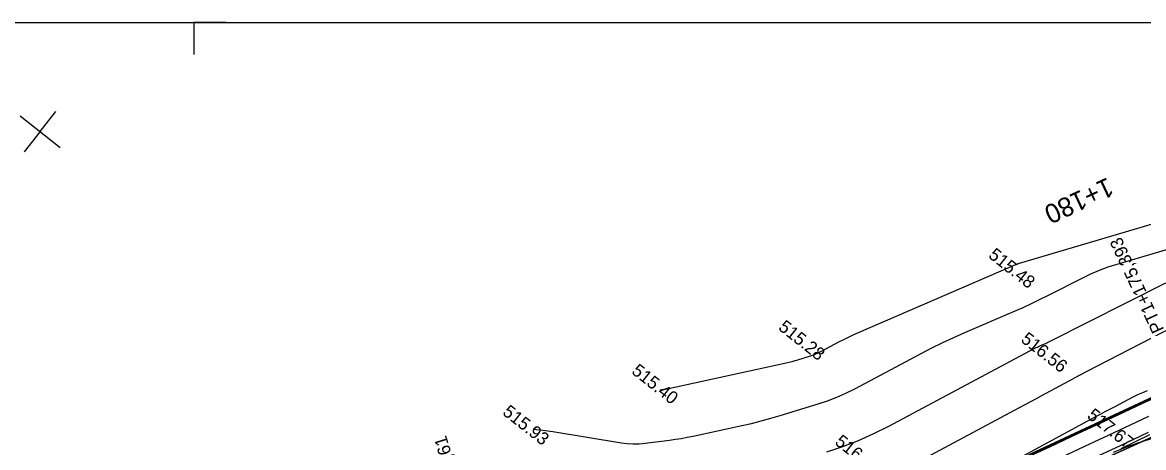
# Model space of a CAD drawing. Extents: x -636600 to -628587, y -1090963 to -1085869.
# Drawn here: x -629664.1 to -629488.6, y -1089625.5 to -1089558.9 of the extents above; entities that cross this region are included whole.
import ezdxf

# ---------------------------------------------------------------- set-up
doc = ezdxf.new("R2010")
doc.units = 0
for name, color, linetype in [('01_PARCELY_NÁVRH_PC', 7, 'Continuous'), ('08_LEGENDA_HV', 7, 'Continuous'), ('42', 7, 'Continuous'), ('Ex_Major Contours', 7, 'Continuous'), ('Ex_Minor Contours', 7, 'Continuous'), ('HEKTOMETRY20', 7, 'Continuous'), ('HL_BODY', 7, 'Continuous'), ('koty_vše', 7, 'Continuous'), ('situace_osa', 7, 'Continuous'), ('situace_těleso', 7, 'Continuous'), ('situace_vozovka', 7, 'Continuous'), ('síť křížků', 7, 'Continuous'), ('VRCHOLY', 7, 'Continuous')]:
    doc.layers.add(name, color=color, linetype=linetype)

msp = doc.modelspace()

# ---------------------------------------------------------------- linework, layer by layer
at = {"layer": '01_PARCELY_NÁVRH_PC'}
for points in [[(-629254.65, -1089739.87), (-629360.83, -1089658.33), (-629368.29, -1089654.33), (-629380.48, -1089650.34), (-629407.53, -1089646.03), (-629420.13, -1089642.95), (-629431.22, -1089638.63), (-629441.36, -1089632.25), (-629463, -1089614.17), (-629469.39, -1089611.97), (-629476.14, -1089612.42), (-629540.5, -1089642.41), (-629554.39, -1089646.51), (-629581.68, -1089651.28), (-629593.36, -1089654.47), (-629629.45, -1089670.47), (-629647.36, -1089680.42), (-629666.29, -1089692.67)], [(-629669.23, -1089703.19), (-629636.5, -1089682.37), (-629594.83, -1089663.56), (-629566.21, -1089655.26), (-629543.03, -1089650.82), (-629502.78, -1089630.85), (-629477.84, -1089619.53), (-629472.37, -1089618.39), (-629466.83, -1089619.34), (-629458.17, -1089625.36), (-629433.24, -1089646.24), (-629378.59, -1089656.96), (-629364.86, -1089662.95), (-629248.8, -1089751.04)]]:
    msp.add_lwpolyline(points, dxfattribs=at)
at = {"layer": '08_LEGENDA_HV'}
msp.add_line((-629847.27, -1089558.93), (-629007.27, -1089558.93), dxfattribs=at)
msp.add_lwpolyline([(-629632.27, -1089558.93), (-629637.27, -1089558.93), (-629637.27, -1089563.93)], dxfattribs=at)
at = {"layer": '42'}
msp.add_line((-629502.78, -1089630.85), (-629476.43, -1089618.89), dxfattribs=at)
at = {"layer": 'Ex_Major Contours'}
msp.add_lwpolyline([(-629488.02, -1089616.61), (-629488.78, -1089616.91), (-629489.54, -1089617.25), (-629490.28, -1089617.61), (-629493.22, -1089619.13), (-629493.96, -1089619.51), (-629494.69, -1089619.89), (-629495.42, -1089620.28), (-629496.15, -1089620.68), (-629508.06, -1089627.15)], dxfattribs=at)
at = {"layer": 'Ex_Minor Contours'}
for points in [[(-629564.27, -1089616.45), (-629564.11, -1089616.43), (-629563.95, -1089616.41), (-629563.79, -1089616.39), (-629563.63, -1089616.36), (-629563.47, -1089616.32), (-629544.55, -1089612.22), (-629544.09, -1089612.11), (-629543.62, -1089612), (-629543.16, -1089611.87), (-629542.71, -1089611.74), (-629540.88, -1089611.18), (-629540.43, -1089611.03), (-629539.99, -1089610.86), (-629539.55, -1089610.67), (-629539.13, -1089610.46), (-629536.18, -1089608.89), (-629535.54, -1089608.56), (-629534.9, -1089608.24), (-629534.26, -1089607.94), (-629533.6, -1089607.65), (-629508.6, -1089596.85), (-629508.55, -1089596.83), (-629508.5, -1089596.81), (-629508.46, -1089596.79), (-629508.41, -1089596.77), (-629508.23, -1089596.67), (-629508.18, -1089596.65), (-629508.13, -1089596.63), (-629508.09, -1089596.61), (-629508.04, -1089596.6), (-629475.72, -1089587.08)], [(-629584.19, -1089622.62), (-629582.64, -1089622.77), (-629582.25, -1089622.81), (-629581.86, -1089622.85), (-629581.48, -1089622.91), (-629581.09, -1089622.97), (-629570.36, -1089624.72), (-629569.43, -1089624.84), (-629568.49, -1089624.89), (-629567.55, -1089624.87), (-629566.61, -1089624.79), (-629562.84, -1089624.32), (-629561.9, -1089624.19), (-629560.96, -1089624.04), (-629560.03, -1089623.87), (-629559.1, -1089623.68), (-629551.51, -1089622.03), (-629549.99, -1089621.69), (-629548.48, -1089621.31), (-629546.98, -1089620.9), (-629545.49, -1089620.47), (-629539.53, -1089618.66), (-629538.06, -1089618.17), (-629536.61, -1089617.61), (-629535.2, -1089616.99), (-629533.81, -1089616.29), (-629523.43, -1089610.77), (-629521.74, -1089609.89), (-629520.04, -1089609.05), (-629518.32, -1089608.24), (-629516.58, -1089607.47), (-629508.82, -1089604.12), (-629507.47, -1089603.53), (-629506.13, -1089602.91), (-629504.79, -1089602.27), (-629503.47, -1089601.61), (-629498.19, -1089598.94), (-629496.86, -1089598.3), (-629495.5, -1089597.73), (-629494.12, -1089597.21), (-629492.72, -1089596.76), (-629477.78, -1089592.36)], [(-629538.19, -1089626.13), (-629535.69, -1089625.31), (-629533.24, -1089624.36), (-629530.84, -1089623.3), (-629528.49, -1089622.12), (-629505.6, -1089609.94), (-629505.41, -1089609.84), (-629505.23, -1089609.75), (-629505.04, -1089609.66), (-629504.85, -1089609.58), (-629504.09, -1089609.25), (-629503.9, -1089609.17), (-629503.72, -1089609.08), (-629503.53, -1089608.99), (-629503.35, -1089608.9), (-629485.14, -1089599.67)], [(-629477.14, -1089603.1), (-629497.58, -1089613.63), (-629498.46, -1089614.08), (-629499.34, -1089614.54), (-629500.21, -1089615.01), (-629501.08, -1089615.48), (-629504.57, -1089617.38), (-629505.44, -1089617.85), (-629506.32, -1089618.32), (-629507.19, -1089618.79), (-629508.07, -1089619.26), (-629524.17, -1089627.86)], [(-629474.56, -1089619.96), (-629489.19, -1089624.67), (-629489.72, -1089624.85), (-629490.25, -1089625.03), (-629490.77, -1089625.23), (-629491.28, -1089625.43), (-629493.35, -1089626.27)]]:
    msp.add_lwpolyline(points, dxfattribs=at)
at = {"layer": 'situace_osa'}
msp.add_lwpolyline([(-629487.82, -1089620.64), (-629488.81, -1089621.1), (-629493.34, -1089623.21), (-629497.87, -1089625.33), (-629502.4, -1089627.44)], dxfattribs=at)
at = {"layer": 'situace_těleso'}
for points in [[(-629507.98, -1089627.32), (-629503.43, -1089625.24), (-629498.88, -1089623.16), (-629494.33, -1089621.09), (-629489.8, -1089618.97), (-629488.82, -1089618.49), (-629485.3, -1089616.78)], [(-629487.69, -1089623.49), (-629492.18, -1089625.7)]]:
    msp.add_lwpolyline(points, dxfattribs=at)
at = {"layer": 'situace_vozovka'}
for points in [[(-629485.23, -1089616.95), (-629488.77, -1089618.6), (-629489.76, -1089619.06), (-629494.29, -1089621.17), (-629498.82, -1089623.29), (-629503.35, -1089625.4), (-629507.88, -1089627.52)], [(-629485.23, -1089616.95), (-629488.77, -1089618.6), (-629489.76, -1089619.06), (-629494.29, -1089621.17), (-629498.82, -1089623.29), (-629503.35, -1089625.4), (-629507.88, -1089627.52)], [(-629487.86, -1089623.14), (-629492.39, -1089625.25), (-629496.92, -1089627.37)], [(-629487.86, -1089623.14), (-629492.39, -1089625.25), (-629496.92, -1089627.37)]]:
    msp.add_lwpolyline(points, dxfattribs=at)
at = {"layer": 'síť křížků'}
for p, q in [((-629664.49, -1089573.55), (-629658.21, -1089578.51)), ((-629661.35, -1089576.03), (-629658.87, -1089572.89)), ((-629661.35, -1089576.03), (-629663.83, -1089579.17))]:
    msp.add_line(p, q, dxfattribs=at)

# ---------------------------------------------------------------- texts
at = {"layer": 'HEKTOMETRY20'}
msp.add_text('1+180', height=3, rotation=205.0047, dxfattribs=at).set_placement((-629494.22, -1089583.11))
at = {"layer": 'HL_BODY'}
msp.add_text('PT1+175,393', height=2, rotation=115.0047, dxfattribs=at).set_placement((-629485.34, -1089607))
at = {"layer": 'koty_vše'}
for s, p in [('515.48', (-629513.02, -1089595.64)), ('515.28', (-629545.91, -1089606.92)), ('516.56', (-629507.95, -1089608.81)), ('515.40', (-629568.89, -1089613.78)), ('515.93', (-629589.1, -1089620.2)), ('517.67', (-629497.58, -1089620.74)), ('516.60', (-629537.07, -1089624.86))]:
    msp.add_text(s, height=2, rotation=321.7265, dxfattribs=at).set_placement(p)
at = {"layer": 'VRCHOLY'}
msp.add_text('V1+291,61', height=2, rotation=107.1593, dxfattribs=at).set_placement((-629593.98, -1089635.91))

doc.saveas('drawing.dxf')
